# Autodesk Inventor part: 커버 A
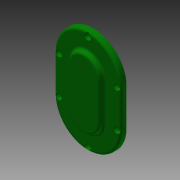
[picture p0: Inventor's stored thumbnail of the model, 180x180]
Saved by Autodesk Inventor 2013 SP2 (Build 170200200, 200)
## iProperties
Created: 2020-04
Part Number: 커버 A
Material: 알루미늄 6061
Document SubType Name: Modeling
Designer: mduedu
Density: 2.71 g/cm^3
Mass: 189.426 g
Surface Area: 209.668 cm^2
Volume: 69.8987 cm^3
Author: mduedu
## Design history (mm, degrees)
sketch "스케치1"
  geometry: L1 (-40, 0)-(-40, -45); L2 (40, 0)-(40, -45); A1 r 40 centre (0, 0) between (40, 0) and (-40, 0); A2 r 40 centre (0, -45) between (-40, -45) and (40, -45); 1 further point
  constraints: 4 end point, 4 point on circle, 4 tangent, 2 centre point, 1 coincident, 1 equal radius, 1 vertical alignment
  dimensions: "d0" = 80 diameter of A1; "d31" = 45 distance of point (0, 0) A2.centre
extrude "돌출1" new body sketch "스케치1" distance "d1" = 7; taper "d2" = 0 deg
fillet "모깎기2" dims "d7" = 3
sketch "스케치4"
  geometry: L1 (30, 0)-(30, -45); L2 (-30, 0)-(-30, -45); A1 r 30 centre (0, 0) between (30, 0) and (-30, 0); A2 r 30 centre (0, -45) between (-30, -45) and (30, -45); 1 further point
  constraints: 4 end point, 4 point on circle, 4 tangent, 2 centre point, 1 coincident, 1 equal radius, 1 vertical alignment
  dimensions: "d19" = 60 diameter of A1; "d38" = 45 distance of point (0, 0) A2.centre
extrude "돌출3" join sketch "스케치4" distance "d20" = 4; taper "d21" = 0 deg
sketch "스케치7"
  geometry: L1 (-20, 0)-(-20, -45); L2 (20, 0)-(20, -45); A1 r 20 centre (0, 0) between (20, 0) and (-20, 0); A2 r 20 centre (0, -45) between (-20, -45) and (20, -45); 1 further point
  constraints: 4 end point, 4 point on circle, 4 tangent, 2 centre point, 1 coincident, 1 equal radius, 1 vertical alignment
  dimensions: "d45" = 40 diameter of A1; "d47" = 45 distance of point (0, 0) A2.centre
extrude "돌출5" join sketch "스케치7" distance "d48" = 5; taper "d49" = -15 deg
fillet "모깎기4" dims "d50" = 3
chamfer "모따기2" distance "d58" = 1; stored, may be unused: second distance "d59" = 2, angle "d60" = 45 deg
sketch "스케치6"
  geometry: L1 (0, 7)-(37, 7) reference; L2 (0, -4)-(30, -4) reference; L3 (0, -4)-(0, 8); L4 (0, 8)-(8, 8); L5 (11, 5)-(11, 5); L6 (11, 5)-(16, 5); L7 (16, 5)-(16, -4); L8 (-45, -4)-(-45, 8); L9 (-45, 8)-(-37, 8); L10 (-34, 5)-(-34, 4); L11 (-34, 4)-(-31, 4); L12 (-31, 4)-(-31, -4); L13 (-31, -4)-(-45, -4); A1 r 3 centre (8, 5) between (11, 5) and (8, 8); A2 r 3 centre (-37, 5) between (-34, 5) and (-37, 8); 3 further points
  constraints: 22 end point, 5 parallel, 5 point on line, 4 perpendicular, 4 point on circle, 4 tangent, 2 centre point, 2 horizontal alignment, 1 horizontal, 1 vertical
  dimensions: "d39" = 32 diameter of L7 L3; "d41" = 3 distance of point (11, 8) L5.end; "d42" = 9 distance of L6.end L7.end; "d43" = 22 diameter of L5 L3; "d44" = 3 radius of A1; "d51" = 8 distance of L11.end L12.end; "d52" = 45 distance of L2.start L8.start; "d53" = 28 diameter of L12 L8; "d54" = 22 diameter of L10 L8; "d55" = 3 radius of A2
revolve "회전1" stored, may be unused: angle "d56" = 90 deg
revolve "회전2" stored, may be unused: angle "d57" = 90 deg
sketch "스케치3"
  geometry: A1 r 35 centre (0, 0) between (0, 35) and (-35, 0); A2 r 35 centre (0, -45) between (-35, -45) and (0, -80); 3 further points
  constraints: 6 point on circle, 5 vertical alignment, 2 centre point, 2 horizontal alignment, 1 coincident, 1 equal radius
  dimensions: "d8" = 70 diameter of A1; "d69" = 45 distance of point (0, 0) A2.centre
hole "구멍1" sketch "스케치3" at (0, 35), (-35, 0), (-35, -45), (0, -80), (35, -45), (35, 0) diameter "d9" = 4.5; stored, may be unused: countersink angle "d13" = 90 deg, drill point angle "d15" = 118 deg; dims "d10" = 6, "d11" = 8, "d12" = 4.4, "d14" = 8
fillet "모깎기5" dims "d70" = 0.3
chamfer "모따기3" distance "d71" = 1; stored, may be unused: second distance "d72" = 2, angle "d73" = 45 deg
node "솔리드1"
